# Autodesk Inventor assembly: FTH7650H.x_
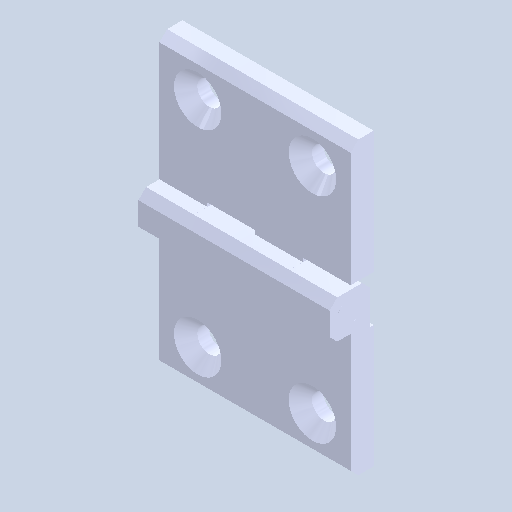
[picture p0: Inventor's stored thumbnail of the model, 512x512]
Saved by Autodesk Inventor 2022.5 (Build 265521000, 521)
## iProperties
Created: 2024-08
Part Number: FTH7650H.x_
Document SubType Name: Assembly
Designer: ImaoCorp
Author: ImaoCorp
Sending System: SOLIDWORKS 2022-2022290
MC: AMD64
MC_MODEL: Intel64 Family 6 Model 60 Stepping 3, GenuineIntel
OS: Windows_NT
FRU: Parasolid Version 33.1, build 260,  4-25-2022
FORMAT: text
GUISE: transmit
KEY: FILEFTH7650H.x_t
DATE: Mon Aug  5 14:46:44 2024
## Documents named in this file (4)
- Y:\5.更新分\2024年対応\0805_FTH\fth7650h\FTH7650H.x_.iam
- Y:\5.更新分\2024年対応\0805_FTH\fth7650h\FTH7650H_01.ipt
- Y:\5.更新分\2024年対応\0805_FTH\fth7650h\FTH7650H_02.ipt
- Y:\5.更新分\2024年対応\0805_FTH\fth7650h\FTH7650H_03.ipt
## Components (3 placed, 3 different names)
1. FTH7650H_01
2. FTH7650H_02
3. FTH7650H_03
